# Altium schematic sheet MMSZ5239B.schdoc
size 127 x 101 mm
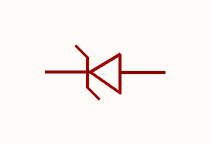
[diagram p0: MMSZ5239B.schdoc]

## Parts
ZD?  mmsz5239b  [SOD-123_L2.8-W1.8-LS3.7-RD]  (value not drawn)

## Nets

Not connected (* = marked no-connect by the designer): ZD? 1(K) 2(A)

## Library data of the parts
ZD? = mmsz5239b: 二极管配置:1个独立式;稳压值(标称值):9.1V;稳压值(范围):8.65V~9.56V;耗散功率(Pd):350mW;; Manufacturer: CJ(江苏长电/长晶); AddInBom: yes; ModelId: 7884390a25fb4c08947731ebfba7e3f8; ModelTransform: 144.8816,62.992,0,0,0,0,0,0,0; Diode Configuration: 1个独立式; Zener Voltage(Nom): 9.1V; Reverse Leakage Current (Ir): 3uA@7V; Pd - Power Dissipation: 350mW; Impedance(Zzt): 10Ω; Impedance(Zzk): 600Ω; Operating Junction Temperature Range: -65℃~+150℃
